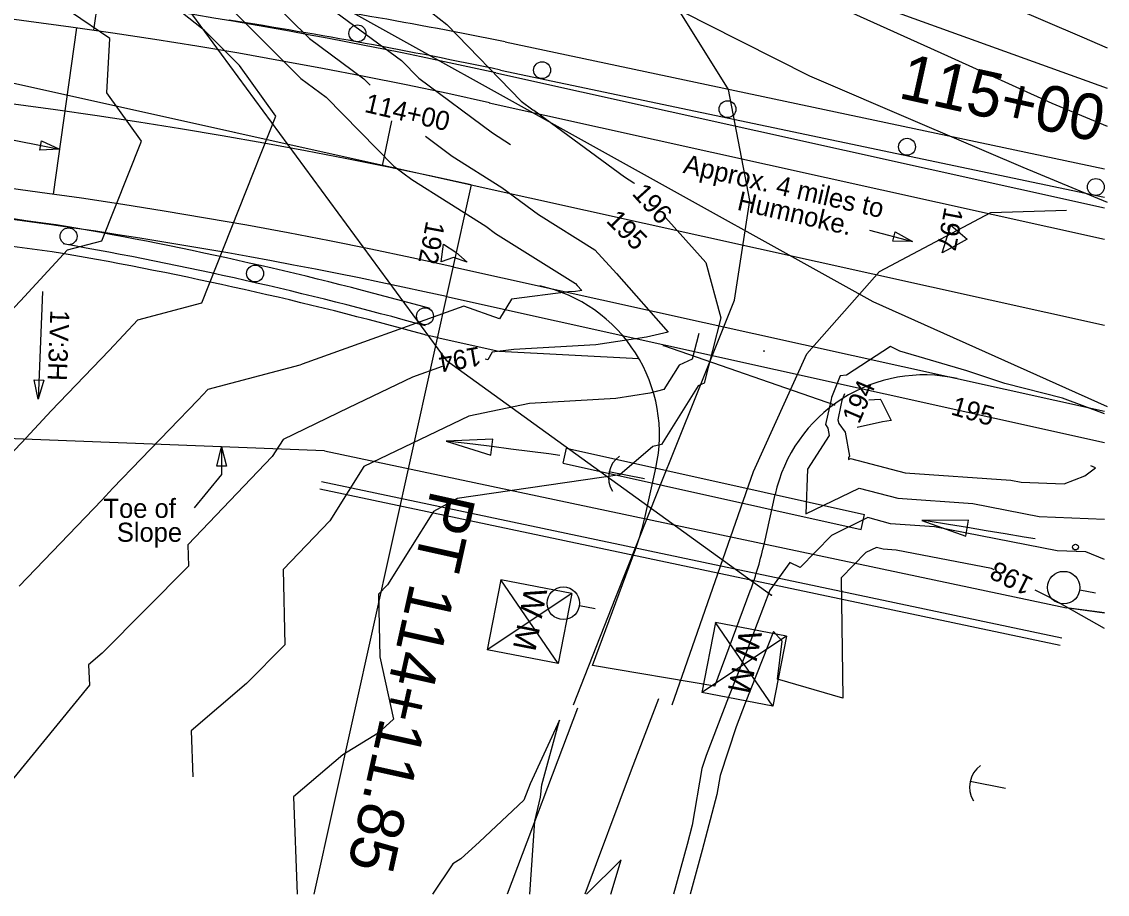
# Model space of a CAD drawing. Extents: x 1385284 to 1385995, y 1975154 to 1975620.
# Drawn here: x 1385605.8 to 1385748, y 1975380.2 to 1975494.4 of the extents above; entities that cross this region are included whole.
import ezdxf

# ---------------------------------------------------------------- set-up
doc = ezdxf.new("R2010")
doc.units = 0
for name, color, linetype in [('Default', 7, 'Continuous'), ('DTM CONTOURS_MAJOR', 7, 'Continuous'), ('DTM_CONTOURS_MINOR', 7, 'Continuous'), ('R_Drainage', 7, 'Continuous'), ('R_Driveway', 7, 'Continuous'), ('R_Guardrail', 7, 'Continuous'), ('R_Horz Alg', 7, 'Continuous'), ('R_Horz Alg Annot', 7, 'Continuous'), ('R_Horz Alg Stationing', 7, 'Continuous'), ('R_Proposed Const Limits', 7, 'Continuous'), ('R_Proposed Road', 7, 'Continuous'), ('R_Shld', 7, 'Continuous'), ('R_Special Ditch', 7, 'Continuous'), ('S_BASELINE', 7, 'Continuous'), ('S_CROSS_DRAIN', 7, 'Continuous'), ('S_DRG_PT_SYM', 7, 'Continuous'), ('S_DRIVEWAY', 7, 'Continuous'), ('S_EDGE_PAVEMENT', 7, 'Continuous'), ('S_MSC_PT_SYM', 7, 'Continuous'), ('S_PAVEMENT_CROWN', 7, 'Continuous'), ('S_UNDERGROUND_CABLE', 7, 'Continuous'), ('S_UTILITY_POLE', 7, 'Continuous'), ('S_UTL_PT_SYM', 7, 'Continuous'), ('S_WATER_UTILITIES', 7, 'Continuous')]:
    doc.layers.add(name, color=color, linetype=linetype)

msp = doc.modelspace()

# ---------------------------------------------------------------- linework, layer by layer
at = {"layer": 'Default'}
for p, q in [((1385598.51, 1975480.21), (1385610.76, 1975477.74)), ((1385716.89, 1975467.15), (1385722.49, 1975465.66)), ((1385608.53, 1975459.1), (1385607.99, 1975445)), ((1385632.01, 1975438.75), (1385632.01, 1975435.16)), ((1385632.01, 1975435.16), (1385628.42, 1975430.77)), ((1385645.08, 1975434.23), (1385742.07, 1975413.75)), ((1385644.87, 1975433.25), (1385741.86, 1975412.77)), ((1385742.89, 1975417.67), (1385747.64, 1975417.01))]:
    msp.add_line(p, q, dxfattribs=at)
for points in [[(1385608.43, 1975478.84), (1385610.76, 1975477.74), (1385608.18, 1975477.62)], [(1385720.23, 1975466.91), (1385722.49, 1975465.66), (1385719.91, 1975465.7)], [(1385608.71, 1975447.48), (1385607.99, 1975445), (1385607.46, 1975447.53)], [(1385631.39, 1975436.25), (1385632.01, 1975438.75), (1385632.64, 1975436.25)]]:
    msp.add_lwpolyline(points, close=True, dxfattribs=at)
at = {"layer": 'DTM CONTOURS_MAJOR'}
for points in [[(1385603.84, 1975543.79), (1385602.41, 1975541.15), (1385602.08, 1975540.14), (1385601.21, 1975538.23), (1385601.15, 1975536.85), (1385603.59, 1975531.9), (1385602.78, 1975529.56), (1385604.44, 1975528.13), (1385614.7, 1975520.56), (1385617.93, 1975517.99), (1385628.31, 1975510.33), (1385631.42, 1975507.86), (1385642.38, 1975499.71), (1385644.65, 1975497.45), (1385655.57, 1975489.36), (1385657.86, 1975487.03), (1385667.49, 1975479.87), (1385669.85, 1975478.37)], [(1385694.52, 1975453.59), (1385693.66, 1975450.24), (1385691.92, 1975449.46), (1385689.92, 1975446.25), (1385688.09, 1975445.78), (1385683.65, 1975445.11), (1385672.34, 1975444.46), (1385664.41, 1975442.79), (1385654.83, 1975438.19), (1385650.65, 1975436.18), (1385646.17, 1975429.09), (1385640.08, 1975422.71), (1385640.27, 1975412.84), (1385635.27, 1975407.79), (1385628, 1975401.57), (1385628.22, 1975395.55)], [(1385713.6, 1975445.69), (1385713.26, 1975444.82), (1385713.14, 1975444.24), (1385712.72, 1975442.32)], [(1385712.72, 1975442.32), (1385712.86, 1975441.81), (1385713.68, 1975440.7), (1385714.24, 1975437.52), (1385714.13, 1975437.35), (1385714.12, 1975437.12), (1385714.39, 1975437.25), (1385721.56, 1975435.37), (1385735.39, 1975434.41), (1385736.75, 1975434.14), (1385742.39, 1975433.92), (1385745.08, 1975434.96), (1385746.49, 1975436.03), (1385745.87, 1975436.28)]]:
    msp.add_lwpolyline(points, dxfattribs=at)
at = {"layer": 'DTM_CONTOURS_MINOR'}
for points in [[(1385579.37, 1975429.79), (1385585.06, 1975435.94), (1385591.29, 1975442.69), (1385595.35, 1975446.9), (1385601.55, 1975453.61), (1385605.67, 1975457.87), (1385611.83, 1975464.54), (1385616.33, 1975465.73), (1385621.49, 1975478.78), (1385616.95, 1975485.14), (1385617.37, 1975492.22), (1385607.3, 1975499.11)], [(1385588.09, 1975420.68), (1385590.61, 1975423.21), (1385594.47, 1975427.38), (1385598.38, 1975431.61), (1385605.84, 1975439.34), (1385609.66, 1975443.48), (1385617.29, 1975451.37), (1385621.02, 1975455.4), (1385629.42, 1975457.63), (1385639.09, 1975482.05), (1385634.35, 1975488.7), (1385629.71, 1975493.32), (1385629.37, 1975493.57), (1385625.23, 1975496.85)], [(1385638.16, 1975497.58), (1385643.52, 1975492.23), (1385650.64, 1975486.96), (1385651.46, 1975486.12)], [(1385658.48, 1975496.41), (1385661.51, 1975494.05), (1385671.24, 1975484.05), (1385672.77, 1975482.91), (1385672.91, 1975482.83), (1385684.79, 1975474.1), (1385686, 1975473.35), (1385686.1, 1975473.24)], [(1385633.93, 1975495.45), (1385642.4, 1975487.01), (1385645.7, 1975484.56), (1385654.58, 1975475.53), (1385656.92, 1975473.79), (1385666.6, 1975467.66), (1385667.9, 1975466.71), (1385678.36, 1975460.17), (1385678.6, 1975459.91), (1385679.18, 1975459.25), (1385678.94, 1975459.19), (1385678.37, 1975459.1), (1385677.45, 1975459.05), (1385670, 1975458.12), (1385668.42, 1975455.51), (1385663.74, 1975457.17), (1385642.54, 1975449.6), (1385642.45, 1975449.56), (1385642.23, 1975449.45), (1385630.2, 1975446.27), (1385628.91, 1975444.87), (1385617.77, 1975433.34), (1385616.33, 1975431.78), (1385605.47, 1975420.53)], [(1385658.71, 1975479.43), (1385662.21, 1975476.83), (1385668.7, 1975472.71), (1385673.53, 1975469.17), (1385680.91, 1975464.56), (1385683.72, 1975461.45), (1385690.49, 1975453.77), (1385687.68, 1975453.11), (1385681.01, 1975452.11), (1385670.3, 1975451.49), (1385667.46, 1975451.14), (1385666.86, 1975450.15), (1385666.54, 1975450.26)], [(1385690.13, 1975468.79), (1385693.96, 1975464.55), (1385695.43, 1975462.89), (1385697.4, 1975455.66), (1385695.2, 1975447.11), (1385694.41, 1975446.75), (1385689.63, 1975439.09), (1385688.51, 1975438.8), (1385684.18, 1975435.08), (1385662.85, 1975432), (1385659.78, 1975430.29), (1385653.72, 1975420.7), (1385652.56, 1975419.49), (1385652.72, 1975411.25), (1385654.51, 1975403.09), (1385652.51, 1975401.25), (1385647.89, 1975398.45), (1385641.42, 1975392.91), (1385641.89, 1975380.2)], [(1385727.53, 1975467.79), (1385729.68, 1975465.94), (1385728.08, 1975465.09), (1385726.41, 1975464.19), (1385727.53, 1975467.79)], [(1385661.07, 1975465.32), (1385662.69, 1975464.27), (1385664.15, 1975462.94), (1385662.4, 1975463.56), (1385660.78, 1975462.98), (1385661.07, 1975465.32)], [(1385747.64, 1975443.09), (1385742.15, 1975445.14), (1385734.58, 1975447.07), (1385729.64, 1975448.7), (1385720.83, 1975451.29), (1385719.61, 1975451.9), (1385713.85, 1975448.13), (1385713.05, 1975448.08), (1385711.91, 1975445.23), (1385711.85, 1975444.97), (1385711.13, 1975441.71)], [(1385660.89, 1975449.28), (1385657.03, 1975447.9), (1385648.64, 1975443.87), (1385640.05, 1975439.74), (1385638.62, 1975437.48), (1385627.6, 1975425.93), (1385627.65, 1975423.14), (1385616.34, 1975411.73), (1385614.58, 1975410.22), (1385614.68, 1975407.55), (1385602.62, 1975392.81), (1385595.92, 1975385.72), (1385589.95, 1975385.61), (1385584.7, 1975380.2)], [(1385718.37, 1975444.94), (1385719.72, 1975442.23), (1385718.59, 1975442.02), (1385715.24, 1975441.28)], [(1385716.8, 1975444.93), (1385718.27, 1975445.02), (1385718.37, 1975444.94)], [(1385711.13, 1975441.71), (1385711.18, 1975441.55), (1385711.43, 1975441.22), (1385711.59, 1975440.26), (1385708.75, 1975435.84), (1385708.55, 1975429.98), (1385715.53, 1975433.37), (1385720.6, 1975432.03), (1385730.39, 1975431.35), (1385739.1, 1975429.65), (1385747.64, 1975429.31)], [(1385747.64, 1975424.03), (1385745.23, 1975425.01), (1385741.46, 1975425.16), (1385725.38, 1975428.3), (1385719.64, 1975428.7), (1385716.67, 1975429.49), (1385711.88, 1975427.16), (1385707.77, 1975422.96), (1385706.46, 1975423.62), (1385703.83, 1975419.98), (1385700.49, 1975411.25), (1385698.42, 1975406), (1385695.49, 1975398.34), (1385694.93, 1975396.63), (1385693.65, 1975389.23), (1385692.98, 1975386.68), (1385691.19, 1975380.2)], [(1385733.21, 1975422.64), (1385732.86, 1975422.81), (1385720.38, 1975425.25), (1385718.68, 1975425.37), (1385717.81, 1975425.6), (1385716.39, 1975424.92), (1385713.18, 1975421.63), (1385713.37, 1975405.84), (1385704.81, 1975408.34), (1385705.43, 1975413.32), (1385704.28, 1975414.59), (1385700.58, 1975405.19), (1385699.39, 1975402.11), (1385697.31, 1975395.74), (1385696.88, 1975393.24), (1385694.95, 1975385.94), (1385693.37, 1975380.2)], [(1385747.64, 1975414.99), (1385740.32, 1975419.12), (1385738.58, 1975419.98)], [(1385672.36, 1975380.2), (1385673.05, 1975389.75), (1385673.77, 1975392.89), (1385673.95, 1975394.48), (1385676.27, 1975402.96), (1385672.42, 1975394.63), (1385671.59, 1975392.51), (1385665.78, 1975387.04), (1385663.35, 1975384.8), (1385662.29, 1975384.17), (1385659.63, 1975380.2)], [(1385683, 1975380.2), (1385684.36, 1975384.7), (1385679.82, 1975380.2)]]:
    msp.add_lwpolyline(points, dxfattribs=at)
at = {"layer": 'R_Drainage'}
for p, q in [((1385676.73, 1975436.62), (1385677.17, 1975438.57)), ((1385677.17, 1975438.57), (1385716.22, 1975429.92)), ((1385676.73, 1975436.62), (1385715.79, 1975427.96)), ((1385715.79, 1975427.96), (1385716.22, 1975429.92))]:
    msp.add_line(p, q, dxfattribs=at)
at = {"layer": 'R_Driveway'}
for p, q in [((1385687.48, 1975429.64), (1385688.88, 1975435.98)), ((1385703.1, 1975426.17), (1385704.5, 1975432.51)), ((1385680.57, 1975410.13), (1385686.25, 1975425.46)), ((1385696.63, 1975407.42), (1385701.25, 1975419.9)), ((1385696.63, 1975407.42), (1385680.57, 1975410.13))]:
    msp.add_line(p, q, dxfattribs=at)
for centre, radius, start, end in [((1385669.36, 1975440.31), 20, 347.4983, 77.4983), ((1385724.03, 1975428.18), 20, 77.4983, 167.4983), ((1385656.24, 1975436.57), 32, 339.689, 347.4983), ((1385656.24, 1975436.57), 48, 339.689, 347.4983)]:
    msp.add_arc(centre, radius, start, end, dxfattribs=at)
at = {"layer": 'R_Guardrail'}
msp.add_line((1385668.53, 1975488.11), (1385747.64, 1975471.46), dxfattribs=at)
for centre in [(1385649.8, 1975492.91), (1385673.98, 1975488.09), (1385698.27, 1975482.98), (1385721.79, 1975478.06), (1385746.52, 1975472.79), (1385611.96, 1975466.33), (1385636.39, 1975461.46), (1385658.65, 1975455.86)]:
    msp.add_circle(centre, 1.11, dxfattribs=at)
for centre, radius, start, end in [((1385522.46, 1974793.81), 709.49, 78.11888, 81.03739), ((1385514.47, 1974795.13), 679.49, 81.7774, 85.38749), ((1385526.24, 1974978.7), 496.34, 74.445, 80.0912), ((1385526.24, 1974978.7), 494, 74.445, 80.0912)]:
    msp.add_arc(centre, radius, start, end, dxfattribs=at)
at = {"layer": 'R_Horz Alg'}
msp.add_line((1385664.69, 1975473.09), (1385747.64, 1975454.7), dxfattribs=at)
msp.add_arc((1385514.36, 1974795.07), 694.49, 77.49826, 106.63511, dxfattribs=at)
at = {"layer": 'R_Horz Alg Annot'}
for p, q in [((1385315.54, 1975550.51), (1385664.69, 1975473.09)), ((1385664.69, 1975473.09), (1385644.1, 1975380.2))]:
    msp.add_line(p, q, dxfattribs=at)
at = {"layer": 'R_Horz Alg Stationing'}
msp.add_line((1385653.1, 1975475.56), (1385654.3, 1975481.44), dxfattribs=at)
at = {"layer": 'R_Proposed Const Limits'}
msp.add_line((1385645.49, 1975438.23), (1385574.72, 1975440.99), dxfattribs=at)
for points in [[(1385645.49, 1975438.23), (1385742.7, 1975417.69)], [(1385747.64, 1975417.01), (1385742.7, 1975417.69)]]:
    msp.add_lwpolyline(points, dxfattribs=at)
at = {"layer": 'R_Proposed Road'}
for p, q in [((1385615.8, 1975497.27), (1385615.22, 1975493.31)), ((1385613, 1975493.63), (1385609.93, 1975471.85)), ((1385667.07, 1975483.83), (1385747.64, 1975465.97)), ((1385662.31, 1975462.35), (1385747.64, 1975443.44))]:
    msp.add_line(p, q, dxfattribs=at)
for radius, end in [(705.49, 106.36838), (683.49, 106.91082)]:
    msp.add_arc((1385514.36, 1974795.07), radius, 77.49826, end, dxfattribs=at)
at = {"layer": 'R_Shld'}
for p, q in [((1385669.17, 1975491.81), (1385747.64, 1975475.15)), ((1385667.94, 1975487.74), (1385747.64, 1975470.07)), ((1385661.45, 1975458.45), (1385747.64, 1975439.34)), ((1385660.25, 1975453.08), (1385668.3, 1975451.3)), ((1385668.3, 1975451.3), (1385686.67, 1975450.33))]:
    msp.add_line(p, q, dxfattribs=at)
for centre, radius, start, end in [((1385514.36, 1974795.07), 709.49, 77.49826, 83.98385), ((1385529.39, 1974796.22), 709.49, 78.63786, 81.55637), ((1385514.36, 1974795.07), 679.49, 77.49826, 85.3781), ((1385514.36, 1974795.07), 675.99, 81.76847, 85.37374), ((1385527.35, 1974979.86), 491.43, 74.5173, 80.1825), ((1385514.68, 1974796.53), 672.49, 77.49826, 77.6482)]:
    msp.add_arc(centre, radius, start, end, dxfattribs=at)
at = {"layer": 'R_Special Ditch'}
for p, q in [((1385667.52, 1975439.78), (1385661.43, 1975439.49)), ((1385667.25, 1975437.68), (1385667.52, 1975439.78)), ((1385661.43, 1975439.49), (1385667.25, 1975437.68)), ((1385729.84, 1975429.16), (1385723.75, 1975429.1)), ((1385723.75, 1975429.1), (1385729.5, 1975427.07)), ((1385729.5, 1975427.07), (1385729.84, 1975429.16))]:
    msp.add_line(p, q, dxfattribs=at)
for points in [[(1385676.32, 1975437.65), (1385674.88, 1975437.84), (1385672.38, 1975438.15), (1385669.89, 1975438.47), (1385667.4, 1975438.79), (1385664.91, 1975439.11), (1385662.27, 1975439.44), (1385661.44, 1975439.49)], [(1385738.56, 1975426.7), (1385737.12, 1975426.94), (1385734.64, 1975427.35), (1385732.16, 1975427.76), (1385729.69, 1975428.18), (1385727.21, 1975428.59), (1385724.58, 1975429.03), (1385723.75, 1975429.1)]]:
    msp.add_lwpolyline(points, dxfattribs=at)
msp.add_circle((1385743.86, 1975425.64), 0.375, dxfattribs=at)
msp.add_circle((1385743.86, 1975425.64), 0.375, dxfattribs=at)
at = {"layer": 'S_BASELINE'}
msp.add_line((1385611.25, 1975535.29), (1385748.02, 1975485.72), dxfattribs=at)
at = {"layer": 'S_CROSS_DRAIN'}
msp.add_line((1385689.87, 1975452.04), (1385712.3, 1975444.26), dxfattribs=at)
at = {"layer": 'S_DRG_PT_SYM'}
for points in [[(1385689.87, 1975452.04), (1385689.92, 1975452.03), (1385689.87, 1975452.04), (1385689.88, 1975452.08), (1385689.87, 1975452.04), (1385689.82, 1975452.04), (1385689.87, 1975452.04), (1385689.86, 1975451.99)], [(1385712.3, 1975444.26), (1385712.34, 1975444.25), (1385712.3, 1975444.26), (1385712.3, 1975444.31), (1385712.3, 1975444.26), (1385712.25, 1975444.27), (1385712.3, 1975444.26), (1385712.29, 1975444.21)]]:
    msp.add_lwpolyline(points, dxfattribs=at)
at = {"layer": 'S_DRIVEWAY'}
for points in [[(1385678.08, 1975404.98), (1385683.65, 1975419.06), (1385689.23, 1975433.14), (1385694.22, 1975445.55), (1385699.21, 1975457.96), (1385701.21, 1975471.01), (1385698.41, 1975485.54), (1385692.15, 1975495.56)], [(1385691.03, 1975404.96), (1385696.35, 1975420.25), (1385701.68, 1975435.54), (1385708.66, 1975450.94), (1385718.19, 1975461.71), (1385732.76, 1975469.43), (1385742.7, 1975469.75)], [(1385689.23, 1975405.76), (1385685.67, 1975396.41), (1385679.6, 1975380.17)], [(1385678.61, 1975404.53), (1385669.42, 1975380.17)]]:
    msp.add_lwpolyline(points, dxfattribs=at)
at = {"layer": 'S_EDGE_PAVEMENT'}
for points in [[(1385611.21, 1975560.34), (1385611.4, 1975560.24), (1385624.47, 1975553.3), (1385624.94, 1975553.05), (1385638.17, 1975545.98), (1385651.4, 1975538.99), (1385664.66, 1975531.98), (1385677.67, 1975524.86), (1385690.83, 1975517.66), (1385704.11, 1975510.96), (1385717.5, 1975504.2), (1385730.91, 1975498.41), (1385744.68, 1975492.46), (1385748.02, 1975491.02)], [(1385602.94, 1975543.48), (1385603.14, 1975543.37), (1385615.83, 1975536.54), (1385628.89, 1975529.16), (1385642.19, 1975522.14), (1385655.49, 1975515.19), (1385668.81, 1975507.91), (1385682.12, 1975501), (1385695.61, 1975494.13), (1385709, 1975487.36), (1385723.17, 1975481.26), (1385736.98, 1975475.38), (1385748.02, 1975470.82)]]:
    msp.add_lwpolyline(points, dxfattribs=at)
at = {"layer": 'S_MSC_PT_SYM'}
msp.add_lwpolyline([(1385703.05, 1975451.31), (1385703.1, 1975451.3), (1385703.05, 1975451.31), (1385703.06, 1975451.36), (1385703.05, 1975451.31), (1385703, 1975451.32), (1385703.05, 1975451.31), (1385703.04, 1975451.26)], dxfattribs=at)
at = {"layer": 'S_PAVEMENT_CROWN'}
msp.add_lwpolyline([(1385607.45, 1975552.41), (1385607.52, 1975552.37), (1385607.52, 1975552.37), (1385620.51, 1975545.21), (1385620.58, 1975545.17), (1385633.72, 1975537.92), (1385646.88, 1975530.73), (1385660.05, 1975523.54), (1385673.34, 1975516.59), (1385686.64, 1975509.64), (1385700.03, 1975502.88), (1385713.42, 1975496.12), (1385727.09, 1975489.95), (1385740.77, 1975483.78), (1385748.02, 1975480.77)], dxfattribs=at)
at = {"layer": 'S_UNDERGROUND_CABLE'}
for p, q in [((1385618.81, 1975512.53), (1385717.29, 1975457.78)), ((1385717.29, 1975457.78), (1385748.02, 1975444.05))]:
    msp.add_line(p, q, dxfattribs=at)
at = {"layer": 'S_UTILITY_POLE'}
for p, q in [((1385687.39, 1975434.58), (1385682.75, 1975435.49)), ((1385744.44, 1975420.04), (1385746.5, 1975419.63)), ((1385678.89, 1975417.99), (1385680.96, 1975417.59)), ((1385734.68, 1975394.04), (1385730.04, 1975394.95))]:
    msp.add_line(p, q, dxfattribs=at)
for centre in [(1385742.31, 1975420.33), (1385676.77, 1975418.28)]:
    msp.add_circle(centre, 2.13, dxfattribs=at)
for centre in [(1385686.1, 1975434.77), (1385733.39, 1975394.23)]:
    msp.add_arc(centre, 3.41, 125.3136, 212.5192, dxfattribs=at)
at = {"layer": 'S_UTL_PT_SYM'}
for points in [[(1385661.42, 1975450.1), (1385661.47, 1975450.09), (1385661.42, 1975450.1), (1385661.43, 1975450.15), (1385661.42, 1975450.1), (1385661.37, 1975450.11), (1385661.42, 1975450.1), (1385661.41, 1975450.05)], [(1385704.02, 1975419.34), (1385704.07, 1975419.33), (1385704.02, 1975419.34), (1385704.03, 1975419.38), (1385704.02, 1975419.34), (1385703.97, 1975419.34), (1385704.02, 1975419.34), (1385704.01, 1975419.29)]]:
    msp.add_lwpolyline(points, dxfattribs=at)
at = {"layer": 'S_WATER_UTILITIES'}
for p, q in [((1385597.3, 1975537.35), (1385661.42, 1975450.1)), ((1385661.42, 1975450.1), (1385704.02, 1975419.34)), ((1385668.57, 1975421.36), (1385666.78, 1975412.2)), ((1385677.89, 1975419.54), (1385668.57, 1975421.36)), ((1385676.09, 1975410.37), (1385668.57, 1975421.36)), ((1385677.89, 1975419.54), (1385666.78, 1975412.2)), ((1385677.89, 1975419.54), (1385676.09, 1975410.37)), ((1385696.71, 1975415.77), (1385694.91, 1975406.61)), ((1385706.02, 1975413.95), (1385696.71, 1975415.77)), ((1385704.23, 1975404.79), (1385696.71, 1975415.77)), ((1385706.02, 1975413.95), (1385694.91, 1975406.61)), ((1385706.02, 1975413.95), (1385704.23, 1975404.79)), ((1385676.09, 1975410.37), (1385666.78, 1975412.2)), ((1385704.23, 1975404.79), (1385694.91, 1975406.61))]:
    msp.add_line(p, q, dxfattribs=at)

# ---------------------------------------------------------------- texts
at = {"layer": 'Default'}
for s, rotation, p in [('114+00', 346.8839, (1385650.6, 1975482.64)), ('Approx. 4 miles to', 347.1501, (1385692.34, 1975474.66)), ('196', 312.14, (1385685.66, 1975471.86)), ('Humnoke.', 347.1501, (1385699.41, 1975469.83)), ('195', 314.8663, (1385682.27, 1975468.28)), ('197', 259.28, (1385726.73, 1975470.25)), ('192', 259.28, (1385658.82, 1975468.44)), ('1V:3H', 267.767, (1385609.58, 1975456.74)), ('194', 189.8421, (1385665.75, 1975451.91)), ('194', 66.8895, (1385715.5, 1975441.66)), ('195', 343.7392, (1385727.42, 1975443.03)), ('198', 153.665, (1385738.49, 1975421.42))]:
    msp.add_text(s, height=2.5, rotation=rotation, dxfattribs=at).set_placement(p)
for s, p in [('Toe of ', (1385616.53, 1975429.46)), ('Slope', (1385618.28, 1975426.33))]:
    msp.add_text(s, height=2.5, dxfattribs=at).set_placement(p)
at = {"layer": 'R_Horz Alg Annot'}
msp.add_text('PT 114+11.85', height=6, rotation=257.4983, dxfattribs=at).set_placement((1385659.45, 1975433.28))
at = {"layer": 'R_Horz Alg Stationing'}
msp.add_text('115+00', height=6, rotation=347.4983, dxfattribs=at).set_placement((1385720.51, 1975484.48))
at = {"layer": 'S_WATER_UTILITIES'}
for p in [(1385671.73, 1975420.53), (1385699.87, 1975414.95)]:
    msp.add_text('W M', height=3, rotation=258.9164, dxfattribs=at).set_placement(p)

doc.saveas('drawing.dxf')
